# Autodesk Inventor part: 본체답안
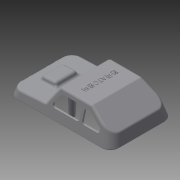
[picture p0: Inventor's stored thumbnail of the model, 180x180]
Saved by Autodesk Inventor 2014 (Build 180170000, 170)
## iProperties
Created: 2015-05
Part Number: 본체답안
Material: 일반
Document SubType Name: Modeling
Designer: Administrator
Density: 1 g/cm^3
Appearance: 기본값
Author: Administrator
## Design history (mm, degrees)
sketch "스케치1"
  geometry: L1 (-61, 38)-(61, 38); L2 (61, 38)-(61, -38); L3 (61, -38)-(-61, -38); L4 (-61, -38)-(-61, 38); 2 further points
  constraints: 8 end point, 2 parallel, 1 coincident, 1 horizontal, 1 perpendicular
  dimensions: "d0" = 122 distance of L2.end L3.end; "d1" = 76 distance of L1.end L2.end
extrude "돌출1" new body sketch "스케치1" distance "d2" = 31; taper "d3" = 0 deg
sketch "스케치2"
  geometry: L1 (122, 0)-(122, 31) reference; L2 (0, 31)-(122, 31) reference; L3 (0, 0)-(0, 31) reference; L4 (0, 0)-(8.306, 31); L5 (0, 0)-(53.771, 0); L6 (122, 0)-(113.694, 31); L7 (122, 0)-(173.56, 0); 1 further point
  constraints: 8 end point, 2 horizontal, 2 point on line
  dimensions: "d4" = 75 deg angle of L5 L4; "d5" = 105 deg angle of L7 L6
extrude "돌출2" cut sketch "스케치2" stored distance "d6" = 31; taper "d7" = 0 deg
sketch "스케치3"
  geometry: L1 (38, 0)-(38, 31) reference; L2 (-38, 0)-(38, 0) reference; L3 (-38, 31)-(-38, 0) reference; L4 (38, 31)-(-38, 31) reference; L5 (-38, 0)-(-29.694, 31); L6 (-38, 0)-(9.597, 0); L7 (38, 0)-(29.694, 31); L8 (38, 0)-(83.57, 0); 1 further point
  constraints: 8 end point, 2 horizontal, 2 point on line
  dimensions: "d8" = 75 deg angle of L6 L5; "d9" = 105 deg angle of L8 L7
extrude "돌출3" cut sketch "스케치3" stored distance "d10" = 31; taper "d11" = 0 deg
sketch "스케치4"
  geometry: L1 (52.694, 31)-(61, 0) reference; L2 (-52.694, 31)-(52.694, 31) reference; L3 (-61, 0)-(-52.694, 31) reference; L4 (61, 0)-(-61, 0) reference; L5 (61, 0)-(61, 9); L6 (58.554, 9.128)-(19, 11.201); L7 (61, 9)-(117.718, 9); L8 (19, 11.201)-(6.628, 31); 1 further point
  constraints: 8 end point, 2 point on line, 1 horizontal, 1 perpendicular
  dimensions: "d12" = 9 distance of L1.end L5.end; "d15" = 177 deg angle of L7 L6; "d16" = 125 deg angle of L8 L6
extrude "돌출4" cut sketch "스케치4" stored distance "d17" = 31; taper "d18" = 0 deg
sketch "스케치5"
  geometry: L1 (19, 11.201)-(6.628, 31) reference; L2 (-52.694, 31)-(6.628, 31) reference; L3 (-61, 0)-(-52.694, 31) reference; L4 (61, 0)-(-61, 0) reference; L5 (58.554, 9.128)-(61, 0) reference; L6 (58.554, 9.128)-(19, 11.201) reference; L7 (-61, 0)-(-61, 31); L8 (-61, 0)-(-30, 0); L9 (-61, 31)-(-31, 31); L10 (-61, 11)-(-31, 31); L11 (-61, 11)-(-61, 31); 1 further point
  constraints: 10 end point, 2 perpendicular, 2 point on line, 1 horizontal
  dimensions: "d19" = 31 distance of L3.start L7.end; "d20" = 90 deg angle of L8 L7 (derived); "d21" = 30 distance of L7.end L9.end
extrude "돌출5" cut sketch "스케치5" stored distance "d24" = 31; taper "d25" = 0 deg
fillet "모깎기1" dims "d26" = 12
fillet "모깎기2" dims "d27" = 3
sketch "스케치6"
  geometry: L1 (-49.409, -38)-(49.409, -38) reference; L2 (61, -26.409)-(61, 26.409) reference; L3 (49.409, 38)-(-49.409, 38) reference; L4 (-61, 26.409)-(-61, -26.409) reference; L5 (-49.409, 37)-(49.409, 37); L6 (60, 26.409)-(60, -26.409); L7 (49.409, -37)-(-49.409, -37); L8 (-60, -26.409)-(-60, 26.409); 5 further points; 4 other entities
  constraints: 8 end point, 7 parallel, 16 other
  dimensions: "d28" = 1 distance between parallel lines of L5 L3
extrude "돌출6" cut sketch "스케치6" distance "d29" = 1; taper "d30" = 0 deg
feature "쉘1" dims "d31" = 2
sketch "스케치7"
  geometry: L1 (4.965, 31)-(-30.092, 31) reference; L2 (18.172, 12.526)-(7.51, 29.59) reference; L3 (-31.756, 30.496)-(-45.887, 21.076) reference; L4 (10.362, 15.59)-(4.738, 24.59); L5 (-30.242, 25.496)-(-43.742, 16.496); L6 (-20.77, 23)-(-20.77, 14); L7 (-20.77, 28.123)-(1.349, 28.123); L8 (-23.986, 23)-(-23.986, 14); L9 (2.194, 26)-(-17.77, 26); L10 (-26.986, 26)-(-28.578, 26); L11 (7.818, 11)-(-17.77, 11); L12 (-26.986, 11)-(-42.078, 11); A1 r 3 centre (2.194, 23) between (4.738, 24.59) and (2.194, 26); A2 r 3 centre (7.818, 14) between (7.818, 11) and (10.362, 15.59); A3 r 3 centre (-17.77, 14) between (-20.77, 14) and (-17.77, 11); A4 r 3 centre (-17.77, 23) between (-17.77, 26) and (-20.77, 23); A5 r 3 centre (-26.986, 23) between (-23.986, 23) and (-26.986, 26); A6 r 3 centre (-28.578, 23) between (-28.578, 26) and (-30.242, 25.496); A7 r 3 centre (-42.078, 14) between (-43.742, 16.496) and (-42.078, 11); A8 r 3 centre (-26.986, 14) between (-26.986, 11) and (-23.986, 14); 3 further points
  constraints: 18 end point, 16 point on circle, 16 tangent, 8 centre point, 8 parallel, 7 equal radius, 4 point on line, 1 horizontal, 1 perpendicular
  dimensions: "d33" = 5 distance between parallel lines of L2 L4; "d34" = 5 distance between parallel lines of L3 L5; "d36" = 90 deg angle of L6 L7; "d37" = 34 distance from line of L6 point (13.23, 11); "d38" = 28 distance from line of L8 point (-51.986, 11); "d39" = 3 radius of A1
extrude "돌출7" cut sketch "스케치7" stored distance "d40" = 1; taper "d41" = 0 deg
sketch "스케치8"
  geometry: L1 (47.554, 9.705)-(27.582, 10.751); L2 (27.582, 10.751)-(29.661, 15.649); L3 (47.554, 9.705)-(45.998, 14.793); L4 (29.661, 15.649)-(45.998, 14.793); 1 further point
  constraints: 8 end point
  dimensions: "d42" = 20 distance of L1.start L1.end; "d43" = 70 deg angle of L1 L2; "d44" = 70 deg angle of L3 L1
extrude "돌출8" join sketch "스케치8" stored distance "d47" = 26; taper "d48" = 0 deg
fillet "모깎기3" dims "d49" = 3
fillet "모깎기4" dims "d50" = 3
fillet "모깎기5" dims "d51" = 3
node "작업 평면1"
sketch "스케치10"
  geometry: L1 (25, 1)-(17, 1); L2 (15, 1)-(7, 1); L3 (-6, 1)-(-14, 1); L4 (-17, 1)-(-25, 1); L5 (26.141, 1)-(-26.141, 1) reference; L6 (0, 1)-(-10, 1); L7 (-10, 1)-(-21, 1); L8 (0, 1)-(11, 1); L9 (11, 1)-(21, 1); A1 r 4 centre (21, 1) between (25, 1) and (17, 1); A2 r 4 centre (11, 1) between (15, 1) and (7, 1); A3 r 4 centre (-10, 1) between (-6, 1) and (-14, 1); A4 r 4 centre (-21, 1) between (-17, 1) and (-25, 1)
  constraints: 16 end point, 8 point on circle, 5 midpoint, 4 centre point, 4 point on line, 3 collinear
  dimensions: "d70" = 8 diameter of A1; "d71" = 8 diameter of A2; "d72" = 8 diameter of A3; "d73" = 8 diameter of A4; "d131" = 10 distance of L6.end L6.start; "d132" = 11 distance of L7.end L6.end; "d133" = 11 distance of L8.end L6.start; "d134" = 10 distance of L9.end L8.end
extrude "돌출9" join sketch "스케치10" stored distance "d74" = 4; taper "d75" = 0 deg
chamfer "모따기1" distance "d76" = 1; stored, may be unused: second distance "d77" = 2, angle "d78" = 45 deg
sketch "스케치11"
  geometry: L1 (-49.141, 1)-(-60.732, 1) reference; L2 (-39.732, 1)-(-39.732, -3.432); L3 (-39.732, 1)-(-42.732, 1); L4 (-42.732, 1)-(-43.911, 34.763); L5 (-39.732, 1)-(-39.732, 34.763); L6 (-39.732, 34.763)-(-43.911, 34.763); L7 (40.268, 1)-(40.268, 13.946); L8 (40.268, 1)-(43.268, 1); L9 (43.268, 1)-(43.72, 13.946); L10 (40.268, 13.946)-(43.72, 13.946); 1 further point
  constraints: 18 end point, 5 perpendicular, 1 parallel
  dimensions: "d79" = 21 distance of L1.end L2.start; "d80" = 80 distance of L2.start L7.start; "d81" = 3 distance of L2.start L3.end; "d82" = 2 deg angle of L5 L4; "d83" = 3 distance of L7.start L8.end; "d84" = 2 deg angle of L9 L7
revolve "회전1" stored, may be unused: angle "d85" = 90 deg
revolve "회전2" stored, may be unused: angle "d86" = 90 deg
sketch "스케치12"
  geometry: L1 (-31.756, 30.496)-(-45.887, 21.076) reference; L2 (-31.756, 30.496)-(-33.423, 37.328); L3 (-33.423, 37.328)-(-51.839, 36.414); L4 (-51.839, 36.414)-(-45.887, 21.076); L5 (-45.887, 21.076)-(-31.756, 30.496); 1 further point
  constraints: 8 end point, 1 collinear
extrude "돌출10" cut sketch "스케치12" stored distance "d87" = 2; taper "d88" = 0 deg
node "작업 평면2"
sketch "스케치13"
  geometry: L1 (-49.141, 1)-(-60.732, 1) reference; L2 (0.268, 1)-(3.268, 1); L3 (3.268, 1)-(4.279, 29.951); L4 (0.268, 1)-(0.268, 29.951); L5 (0.268, 1)-(29.219, 1); L6 (0.268, 29.951)-(4.279, 29.951); 1 further point
  constraints: 10 end point, 2 perpendicular, 1 horizontal
  dimensions: "d90" = 61 distance of L1.end L2.start; "d91" = 3 distance of L2.start L2.end; "d92" = 90 deg angle of L5 L4; "d93" = 2 deg angle of L3 L4
revolve "회전3" sketch "스케치13" stored, may be unused: angle "d94" = 90 deg
hole "구멍1" diameter "d97" = 3.242; stored, may be unused: countersink angle "d101" = 90 deg, drill point angle "d103" = 118 deg; dims "d95" = 10, "d96" = 10, "d98" = 9, "d99" = 4, "d100" = 2, "d102" = 11
hole "구멍2" diameter "d106" = 3.242; stored, may be unused: countersink angle "d110" = 90 deg, drill point angle "d112" = 118 deg; dims "d104" = 10, "d105" = 10, "d107" = 9, "d108" = 4, "d109" = 2, "d111" = 11
hole "구멍3" diameter "d115" = 3.242; stored, may be unused: countersink angle "d119" = 90 deg, drill point angle "d121" = 118 deg; dims "d113" = 10, "d114" = 10, "d116" = 9, "d117" = 4, "d118" = 2, "d120" = 11
hole "구멍4" diameter "d124" = 3.242; stored, may be unused: countersink angle "d128" = 90 deg, drill point angle "d130" = 118 deg; dims "d122" = 10, "d123" = 10, "d125" = 9, "d126" = 4, "d127" = 2, "d129" = 11
sketch "스케치14"
  geometry: L1 (60.732, -26.141)-(60.732, 26.141) reference; L2 (60.732, 0)-(10.732, 0); 2 further points
  constraints: 2 end point, 1 coincident, 1 midpoint, 1 perpendicular, 1 other
  dimensions: "d135" = 50 distance of L2.start L2.end
feature "엠보싱1" sketch "스케치14" dims "d0" = 122, "d1" = 76, "d136" = 0.5, "d137" = 0
node "솔리드1"
mirror "대칭1"
node "투영된 루프1"
node "투영된 루프2"
node "투영된 루프3"
other parameters: "d32" = 5, "d35" = 15, "d52" = -61, "d89" = 22
